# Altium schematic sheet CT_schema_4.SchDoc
size 300 x 163 mm
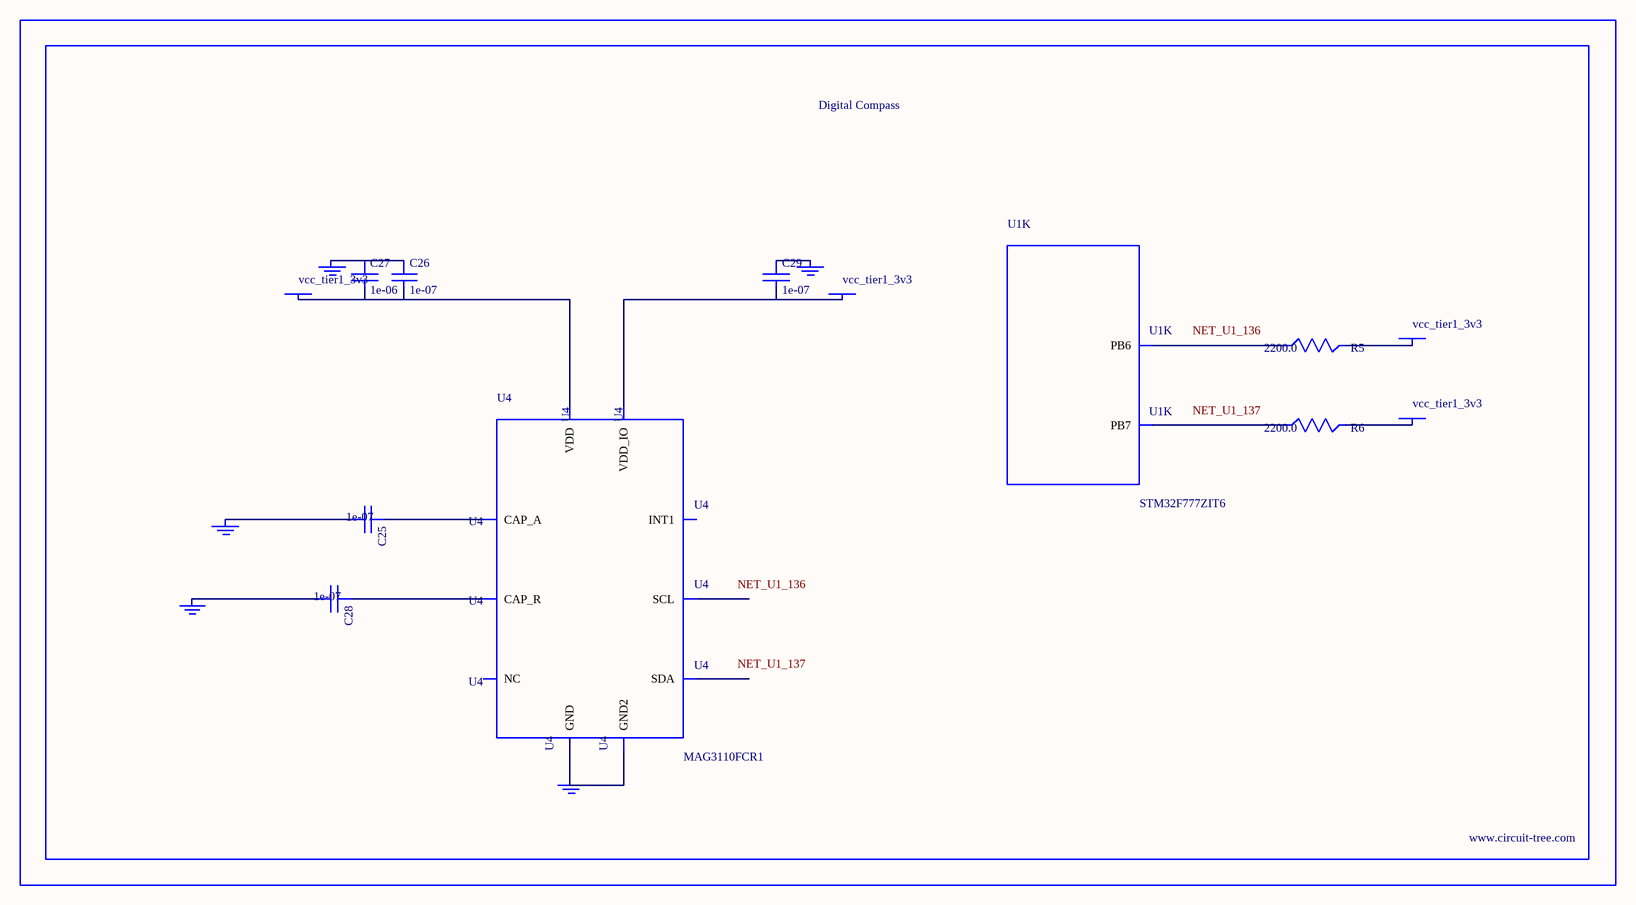
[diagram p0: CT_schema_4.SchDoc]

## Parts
BORDER3  (no value)
C25  1e-07  [C0402]
C26  1e-07  [C0402]
C27  1e-06  [C0603]
C28  1e-07  [C0402]
C29  1e-07  [C0402]
GND_INSTANCE_3_0  (no value)
GND_INSTANCE_3_1  (no value)
GND_INSTANCE_3_2  (no value)
GND_INSTANCE_3_3  (no value)
GND_INSTANCE_3_4  (no value)
POWER_INSTANCE_3_0  vcc_tier1_3v3
POWER_INSTANCE_3_1  vcc_tier1_3v3
POWER_INSTANCE_3_2  vcc_tier1_3v3
POWER_INSTANCE_3_3  vcc_tier1_3v3
R5  2200.0  [R0603]
R6  2200.0  [R0603]
U1  STM32F777ZIT6  [LQFP144]  (part K of 13)
U4  MAG3110FCR1  [DFN-10]

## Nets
NetC25_1: C25.1 U4.1(CAP_A)
NetC25_2: C25.2 GND_INSTANCE_3_0.0(GND)
NetC26_1: C26.1 C27.1 GND_INSTANCE_3_1.0(GND)
NetC26_2: C26.2 C27.2 POWER_INSTANCE_3_0.0(PWR) U4.2(VDD)
NetC28_1: C28.1 U4.4(CAP_R)
NetC28_2: C28.2 GND_INSTANCE_3_2.0(GND)
NetC29_1: C29.1 GND_INSTANCE_3_3.0(GND)
NetC29_2: C29.2 POWER_INSTANCE_3_1.0(PWR) U4.8(VDD_IO)
NetGND_INSTANCE_3_4_0: GND_INSTANCE_3_4.0(GND) U4.5(GND) U4.10(GND2)
NetPOWER_INSTANCE_3_2_0: POWER_INSTANCE_3_2.0(PWR) R5.2
NetPOWER_INSTANCE_3_3_0: POWER_INSTANCE_3_3.0(PWR) R6.2
NetR5_1: R5.1 U1.136(PB6)
NetR6_1: R6.1 U1.137(PB7)

Not connected (* = marked no-connect by the designer): U4 3(NC) 6(SDA) 7(SCL) 9(INT1)

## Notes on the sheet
- Labels drawn without touching a wire or pin: NET_U1_136, NET_U1_137

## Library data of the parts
BORDER3 = BORDER_PAGE3
C25 C26 C28 C29 = C0402C104K3RACTU
C27 = C0603C105K3RACTU
GND_INSTANCE_3_0-GND_INSTANCE_3_4 = GND
POWER_INSTANCE_3_0-POWER_INSTANCE_3_3 = PWR
R5 R6 = RC0603JR-072K2L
